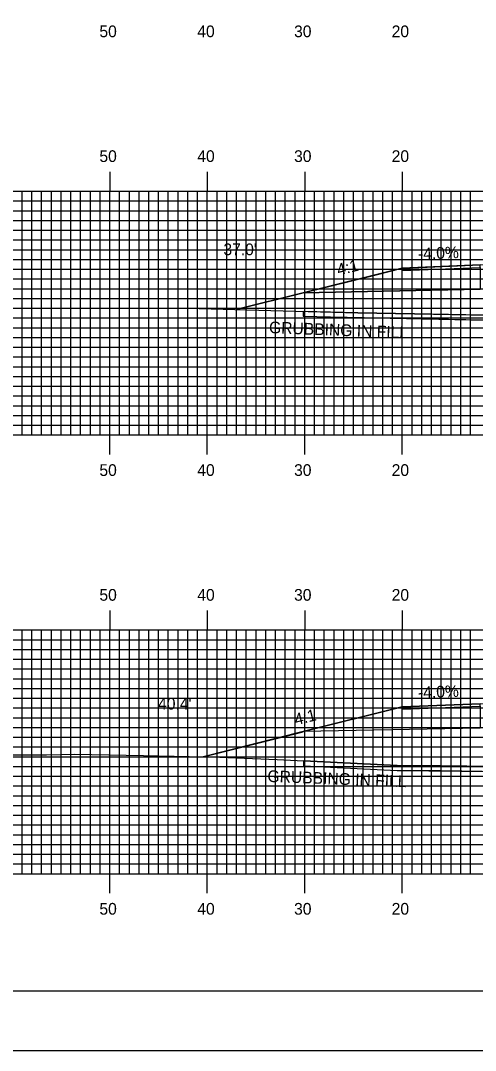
# Model space of a CAD drawing. Extents: x 1763759 to 1764102, y 442591 to 442811.
# Drawn here: x 1763865.2 to 1763911.8, y 442590.5 to 442696.2 of the extents above; entities that cross this region are included whole.
import ezdxf

# ---------------------------------------------------------------- set-up
doc = ezdxf.new("R2010")
doc.units = 0
for name, color, linetype in [('ANNOTATION', 7, 'Continuous'), ('BORDER', 7, 'Continuous'), ('D_Roadway_Centerline', 7, 'Continuous'), ('D_Roadway_Edge_Shoulder', 7, 'Continuous'), ('D_Roadway_SlopeLines', 7, 'Continuous'), ('D_Roadway_SubGrade', 7, 'Continuous'), ('D_Text_Standard', 7, 'Continuous'), ('GRUBBING IN FILL', 7, 'Continuous'), ('H_V ANNOTATION', 7, 'Continuous'), ('MAJOR', 7, 'Continuous'), ('MINOR', 7, 'Continuous'), ('PLOT BOUNDARY', 7, 'Continuous'), ('S_Roadway_Centerline', 7, 'Continuous')]:
    doc.layers.add(name, color=color, linetype=linetype)

msp = doc.modelspace()

# ---------------------------------------------------------------- linework, layer by layer
at = {"layer": 'BORDER'}
msp.add_lwpolyline([(1763774.72, 442596.67), (1764094.72, 442596.67), (1764094.72, 442806.67), (1763774.72, 442806.67)], close=True, dxfattribs=at)
at = {"layer": 'D_Roadway_Centerline'}
for points in [[(1763887.29, 442666.53), (1763894.14, 442668.24), (1763894.15, 442668.24), (1763901.63, 442670.11), (1763904.32, 442670.79), (1763906.87, 442670.89), (1763912.31, 442671.11), (1763912.32, 442671.11), (1763924.31, 442671.35), (1763924.32, 442671.35), (1763924.32, 442671.35), (1763936.32, 442671.27), (1763936.32, 442671.27), (1763940.22, 442671.11), (1763944.32, 442670.95), (1763944.33, 442670.95), (1763950.59, 442669.38), (1763954.49, 442668.4), (1763955.16, 442668.24), (1763956.32, 442667.95), (1763964.82, 442665.82), (1763964.98, 442665.78)], [(1763883.9, 442620.67), (1763894.14, 442623.23), (1763894.14, 442623.24), (1763904.32, 442625.78), (1763904.32, 442625.78), (1763912.31, 442626.1), (1763912.32, 442626.1), (1763919.08, 442626.24), (1763924.31, 442626.34), (1763924.32, 442626.34), (1763936.31, 442626.5), (1763936.32, 442626.5), (1763936.32, 442626.5), (1763944.32, 442626.18), (1763954.49, 442623.64), (1763954.49, 442623.63), (1763956.32, 442623.18), (1763957.04, 442623), (1763968.66, 442620.09)]]:
    msp.add_lwpolyline(points, dxfattribs=at)
at = {"layer": 'D_Roadway_Edge_Shoulder'}
for points in [[(1763912.32, 442671.11), (1763904.32, 442670.79), (1763904.32, 442670.54), (1763912.32, 442670.86)], [(1763912.32, 442626.1), (1763904.32, 442625.78), (1763904.32, 442625.53), (1763912.32, 442625.85)]]:
    msp.add_lwpolyline(points, close=True, dxfattribs=at)
at = {"layer": 'D_Roadway_SlopeLines'}
for points in [[(1763904.32, 442670.79), (1763894.14, 442668.24), (1763887.29, 442666.53)], [(1763904.32, 442625.78), (1763894.14, 442623.24), (1763883.9, 442620.67)]]:
    msp.add_lwpolyline(points, dxfattribs=at)
at = {"layer": 'D_Roadway_SubGrade'}
for points in [[(1763904.32, 442670.54), (1763912.32, 442670.86), (1763912.32, 442670.44), (1763912.32, 442668.61), (1763894.14, 442668.24), (1763904.32, 442670.79)], [(1763904.32, 442625.53), (1763912.32, 442625.85), (1763912.32, 442625.43), (1763912.32, 442623.6), (1763894.14, 442623.24), (1763904.32, 442625.78)]]:
    msp.add_lwpolyline(points, close=True, dxfattribs=at)
at = {"layer": 'GRUBBING IN FILL'}
for p, q in [((1763894.14, 442666.35), (1763894.14, 442665.85)), ((1763894.22, 442619.74), (1763894.22, 442620.24))]:
    msp.add_line(p, q, dxfattribs=at)
for points in [[(1763894.14, 442668.24), (1763912.32, 442668.61), (1763924.32, 442668.85), (1763936.32, 442668.77), (1763954.49, 442668.4)], [(1763894.14, 442665.85), (1763899.76, 442665.71), (1763911.39, 442665.49), (1763917.28, 442665.37), (1763922.81, 442665.34), (1763935.01, 442665.23), (1763940.12, 442665.08), (1763952.29, 442665.22), (1763953.27, 442665.24), (1763953.7, 442665.26), (1763954.47, 442665.25)], [(1763894.22, 442619.74), (1763903.78, 442619.27), (1763908.34, 442619.25), (1763918.82, 442619.1), (1763922.15, 442619.08), (1763924.62, 442619.11), (1763939.47, 442619.52), (1763954.47, 442619.78)]]:
    msp.add_lwpolyline(points, dxfattribs=at)
for points in [[(1763894.14, 442666.35), (1763894.14, 442665.85), (1763896.95, 442665.78), (1763905.58, 442665.6), (1763914.34, 442665.43), (1763920.05, 442665.35), (1763924.32, 442665.32), (1763924.32, 442665.82), (1763920.05, 442665.85), (1763914.34, 442665.93), (1763905.58, 442666.1), (1763899.76, 442666.21)], [(1763894.14, 442666.35), (1763894.14, 442665.85), (1763896.95, 442665.78), (1763905.58, 442665.6), (1763914.34, 442665.43), (1763920.05, 442665.35), (1763924.32, 442665.32), (1763924.32, 442665.82), (1763920.05, 442665.85), (1763914.34, 442665.93), (1763905.58, 442666.1), (1763899.76, 442666.21)], [(1763894.22, 442619.74), (1763903.78, 442619.27), (1763913.58, 442619.17), (1763916.38, 442619.14), (1763917.03, 442619.13), (1763918.6, 442619.1), (1763920.48, 442619.09), (1763924.32, 442619.1), (1763924.32, 442619.6), (1763920.48, 442619.59), (1763918.82, 442619.6), (1763913.58, 442619.67), (1763908.34, 442619.75), (1763903.78, 442619.77), (1763897.63, 442620.07), (1763894.22, 442620.24)], [(1763894.22, 442619.74), (1763903.78, 442619.27), (1763913.58, 442619.17), (1763916.38, 442619.14), (1763917.03, 442619.13), (1763918.6, 442619.1), (1763920.48, 442619.09), (1763924.32, 442619.1), (1763924.32, 442619.6), (1763920.48, 442619.59), (1763918.82, 442619.6), (1763913.58, 442619.67), (1763908.34, 442619.75), (1763903.78, 442619.77), (1763897.63, 442620.07), (1763894.22, 442620.24)]]:
    msp.add_lwpolyline(points, close=True, dxfattribs=at)
at = {"layer": 'MAJOR'}
for p, q in [((1763874.32, 442680.67), (1763874.32, 442678.67)), ((1763884.32, 442680.67), (1763884.32, 442678.67)), ((1763894.32, 442680.67), (1763894.32, 442678.67)), ((1763904.32, 442680.67), (1763904.32, 442678.67)), ((1763784.32, 442678.67), (1764064.32, 442678.67)), ((1763784.32, 442678.67), (1764064.32, 442678.67)), ((1763874.32, 442653.67), (1763874.32, 442678.67)), ((1763884.32, 442653.67), (1763884.32, 442678.67)), ((1763894.32, 442653.67), (1763894.32, 442678.67)), ((1763904.32, 442653.67), (1763904.32, 442678.67)), ((1763784.32, 442673.67), (1764064.32, 442673.67)), ((1763784.32, 442668.67), (1764064.32, 442668.67)), ((1763784.32, 442663.67), (1764064.32, 442663.67)), ((1763784.32, 442658.67), (1764064.32, 442658.67)), ((1763784.32, 442653.67), (1764064.32, 442653.67)), ((1763784.32, 442653.67), (1764064.32, 442653.67)), ((1763874.32, 442651.66), (1763874.32, 442653.67)), ((1763884.32, 442651.66), (1763884.32, 442653.67)), ((1763894.32, 442651.66), (1763894.32, 442653.67)), ((1763904.32, 442651.66), (1763904.32, 442653.67)), ((1763874.32, 442635.67), (1763874.32, 442633.67)), ((1763884.32, 442635.67), (1763884.32, 442633.67)), ((1763894.32, 442635.67), (1763894.32, 442633.67)), ((1763904.32, 442635.67), (1763904.32, 442633.67)), ((1763784.32, 442633.67), (1764064.32, 442633.67)), ((1763784.32, 442633.67), (1764064.32, 442633.67)), ((1763874.32, 442608.67), (1763874.32, 442633.67)), ((1763884.32, 442608.67), (1763884.32, 442633.67)), ((1763894.32, 442608.67), (1763894.32, 442633.67)), ((1763904.32, 442608.67), (1763904.32, 442633.67)), ((1763784.32, 442628.67), (1764064.32, 442628.67)), ((1763784.32, 442623.67), (1764064.32, 442623.67)), ((1763784.32, 442618.67), (1764064.32, 442618.67)), ((1763784.32, 442613.67), (1764064.32, 442613.67)), ((1763784.32, 442608.67), (1764064.32, 442608.67)), ((1763784.32, 442608.67), (1764064.32, 442608.67)), ((1763874.32, 442606.66), (1763874.32, 442608.67)), ((1763884.32, 442606.66), (1763884.32, 442608.67)), ((1763894.32, 442606.66), (1763894.32, 442608.67)), ((1763904.32, 442606.66), (1763904.32, 442608.67))]:
    msp.add_line(p, q, dxfattribs=at)
at = {"layer": 'MINOR'}
for p, q in [((1763865.32, 442653.67), (1763865.32, 442678.67)), ((1763866.32, 442653.67), (1763866.32, 442678.67)), ((1763867.32, 442653.67), (1763867.32, 442678.67)), ((1763868.32, 442653.67), (1763868.32, 442678.67)), ((1763869.32, 442653.67), (1763869.32, 442678.67)), ((1763870.32, 442653.67), (1763870.32, 442678.67)), ((1763871.32, 442653.67), (1763871.32, 442678.67)), ((1763872.32, 442653.67), (1763872.32, 442678.67)), ((1763873.32, 442653.67), (1763873.32, 442678.67)), ((1763875.32, 442653.67), (1763875.32, 442678.67)), ((1763876.32, 442653.67), (1763876.32, 442678.67)), ((1763877.32, 442653.67), (1763877.32, 442678.67)), ((1763878.32, 442653.67), (1763878.32, 442678.67)), ((1763879.32, 442653.67), (1763879.32, 442678.67)), ((1763880.32, 442653.67), (1763880.32, 442678.67)), ((1763881.32, 442653.67), (1763881.32, 442678.67)), ((1763882.32, 442653.67), (1763882.32, 442678.67)), ((1763883.32, 442653.67), (1763883.32, 442678.67)), ((1763885.32, 442653.67), (1763885.32, 442678.67)), ((1763886.32, 442653.67), (1763886.32, 442678.67)), ((1763887.32, 442653.67), (1763887.32, 442678.67)), ((1763888.32, 442653.67), (1763888.32, 442678.67)), ((1763889.32, 442653.67), (1763889.32, 442678.67)), ((1763890.32, 442653.67), (1763890.32, 442678.67)), ((1763891.32, 442653.67), (1763891.32, 442678.67)), ((1763892.32, 442653.67), (1763892.32, 442678.67)), ((1763893.32, 442653.67), (1763893.32, 442678.67)), ((1763895.32, 442653.67), (1763895.32, 442678.67)), ((1763896.32, 442653.67), (1763896.32, 442678.67)), ((1763897.32, 442653.67), (1763897.32, 442678.67)), ((1763898.32, 442653.67), (1763898.32, 442678.67)), ((1763899.32, 442653.67), (1763899.32, 442678.67)), ((1763900.32, 442653.67), (1763900.32, 442678.67)), ((1763901.32, 442653.67), (1763901.32, 442678.67)), ((1763902.32, 442653.67), (1763902.32, 442678.67)), ((1763903.32, 442653.67), (1763903.32, 442678.67)), ((1763905.32, 442653.67), (1763905.32, 442678.67)), ((1763906.32, 442653.67), (1763906.32, 442678.67)), ((1763907.32, 442653.67), (1763907.32, 442678.67)), ((1763908.32, 442653.67), (1763908.32, 442678.67)), ((1763909.32, 442653.67), (1763909.32, 442678.67)), ((1763910.32, 442653.67), (1763910.32, 442678.67)), ((1763911.32, 442653.67), (1763911.32, 442678.67)), ((1763784.32, 442677.67), (1764064.32, 442677.67)), ((1763784.32, 442676.67), (1764064.32, 442676.67)), ((1763784.32, 442675.67), (1764064.32, 442675.67)), ((1763784.32, 442674.67), (1764064.32, 442674.67)), ((1763784.32, 442672.67), (1764064.32, 442672.67)), ((1763784.32, 442671.67), (1764064.32, 442671.67)), ((1763784.32, 442670.67), (1764064.32, 442670.67)), ((1763784.32, 442669.67), (1764064.32, 442669.67)), ((1763784.32, 442667.67), (1764064.32, 442667.67)), ((1763784.32, 442666.67), (1764064.32, 442666.67)), ((1763784.32, 442665.67), (1764064.32, 442665.67)), ((1763784.32, 442664.67), (1764064.32, 442664.67)), ((1763784.32, 442662.67), (1764064.32, 442662.67)), ((1763784.32, 442661.67), (1764064.32, 442661.67)), ((1763784.32, 442660.67), (1764064.32, 442660.67)), ((1763784.32, 442659.67), (1764064.32, 442659.67)), ((1763784.32, 442657.67), (1764064.32, 442657.67)), ((1763784.32, 442656.67), (1764064.32, 442656.67)), ((1763784.32, 442655.67), (1764064.32, 442655.67)), ((1763784.32, 442654.67), (1764064.32, 442654.67)), ((1763865.32, 442608.67), (1763865.32, 442633.67)), ((1763866.32, 442608.67), (1763866.32, 442633.67)), ((1763867.32, 442608.67), (1763867.32, 442633.67)), ((1763868.32, 442608.67), (1763868.32, 442633.67)), ((1763869.32, 442608.67), (1763869.32, 442633.67)), ((1763870.32, 442608.67), (1763870.32, 442633.67)), ((1763871.32, 442608.67), (1763871.32, 442633.67)), ((1763872.32, 442608.67), (1763872.32, 442633.67)), ((1763873.32, 442608.67), (1763873.32, 442633.67)), ((1763875.32, 442608.67), (1763875.32, 442633.67)), ((1763876.32, 442608.67), (1763876.32, 442633.67)), ((1763877.32, 442608.67), (1763877.32, 442633.67)), ((1763878.32, 442608.67), (1763878.32, 442633.67)), ((1763879.32, 442608.67), (1763879.32, 442633.67)), ((1763880.32, 442608.67), (1763880.32, 442633.67)), ((1763881.32, 442608.67), (1763881.32, 442633.67)), ((1763882.32, 442608.67), (1763882.32, 442633.67)), ((1763883.32, 442608.67), (1763883.32, 442633.67)), ((1763885.32, 442608.67), (1763885.32, 442633.67)), ((1763886.32, 442608.67), (1763886.32, 442633.67)), ((1763887.32, 442608.67), (1763887.32, 442633.67)), ((1763888.32, 442608.67), (1763888.32, 442633.67)), ((1763889.32, 442608.67), (1763889.32, 442633.67)), ((1763890.32, 442608.67), (1763890.32, 442633.67)), ((1763891.32, 442608.67), (1763891.32, 442633.67)), ((1763892.32, 442608.67), (1763892.32, 442633.67)), ((1763893.32, 442608.67), (1763893.32, 442633.67)), ((1763895.32, 442608.67), (1763895.32, 442633.67)), ((1763896.32, 442608.67), (1763896.32, 442633.67)), ((1763897.32, 442608.67), (1763897.32, 442633.67)), ((1763898.32, 442608.67), (1763898.32, 442633.67)), ((1763899.32, 442608.67), (1763899.32, 442633.67)), ((1763900.32, 442608.67), (1763900.32, 442633.67)), ((1763901.32, 442608.67), (1763901.32, 442633.67)), ((1763902.32, 442608.67), (1763902.32, 442633.67)), ((1763903.32, 442608.67), (1763903.32, 442633.67)), ((1763905.32, 442608.67), (1763905.32, 442633.67)), ((1763906.32, 442608.67), (1763906.32, 442633.67)), ((1763907.32, 442608.67), (1763907.32, 442633.67)), ((1763908.32, 442608.67), (1763908.32, 442633.67)), ((1763909.32, 442608.67), (1763909.32, 442633.67)), ((1763910.32, 442608.67), (1763910.32, 442633.67)), ((1763911.32, 442608.67), (1763911.32, 442633.67)), ((1763784.32, 442632.67), (1764064.32, 442632.67)), ((1763784.32, 442631.67), (1764064.32, 442631.67)), ((1763784.32, 442630.67), (1764064.32, 442630.67)), ((1763784.32, 442629.67), (1764064.32, 442629.67)), ((1763784.32, 442627.67), (1764064.32, 442627.67)), ((1763784.32, 442626.67), (1764064.32, 442626.67)), ((1763784.32, 442625.67), (1764064.32, 442625.67)), ((1763784.32, 442624.67), (1764064.32, 442624.67)), ((1763784.32, 442622.67), (1764064.32, 442622.67)), ((1763784.32, 442621.67), (1764064.32, 442621.67)), ((1763784.32, 442620.67), (1764064.32, 442620.67)), ((1763784.32, 442619.67), (1764064.32, 442619.67)), ((1763784.32, 442617.67), (1764064.32, 442617.67)), ((1763784.32, 442616.67), (1764064.32, 442616.67)), ((1763784.32, 442615.67), (1764064.32, 442615.67)), ((1763784.32, 442614.67), (1764064.32, 442614.67)), ((1763784.32, 442612.67), (1764064.32, 442612.67)), ((1763784.32, 442611.67), (1764064.32, 442611.67)), ((1763784.32, 442610.67), (1764064.32, 442610.67)), ((1763784.32, 442609.67), (1764064.32, 442609.67))]:
    msp.add_line(p, q, dxfattribs=at)
at = {"layer": 'PLOT BOUNDARY'}
msp.add_lwpolyline([(1763758.53, 442590.55), (1764098.53, 442590.55), (1764098.53, 442810.55), (1763758.53, 442810.55)], close=True, dxfattribs=at)
at = {"layer": 'S_Roadway_Centerline'}
for points in [[(1763863.88, 442666.68), (1763865.48, 442666.68), (1763869.39, 442666.69), (1763882.25, 442666.67), (1763890.84, 442666.43), (1763899.76, 442666.21), (1763911.39, 442665.99), (1763917.28, 442665.87), (1763922.81, 442665.84), (1763935.01, 442665.73), (1763940.12, 442665.58), (1763952.29, 442665.72), (1763953.27, 442665.74), (1763953.7, 442665.76), (1763954.72, 442665.75), (1763971.09, 442665.8)], [(1763860.52, 442620.85), (1763867.82, 442620.86), (1763870.65, 442620.92), (1763877.79, 442620.81), (1763885.59, 442620.64), (1763891.48, 442620.37), (1763903.78, 442619.77), (1763908.34, 442619.75), (1763918.82, 442619.6), (1763922.15, 442619.58), (1763924.62, 442619.61), (1763939.47, 442620.02), (1763954.56, 442620.28), (1763957.18, 442620.29), (1763960.52, 442620.37), (1763975.15, 442619.87)]]:
    msp.add_lwpolyline(points, dxfattribs=at)

# ---------------------------------------------------------------- texts
at = {"layer": 'ANNOTATION'}
for s, rotation, p in [('-4.0%', 2.2906, (1763905.95, 442671.65)), ('4:1', 14.0336, (1763897.77, 442670.01)), ('-4.0%', 2.2905, (1763905.95, 442626.65)), ('4:1', 14.0394, (1763893.42, 442623.88))]:
    msp.add_text(s, height=1.2, rotation=rotation, dxfattribs=at).set_placement(p)
at = {"layer": 'D_Text_Standard'}
for s, p in [("37.0'", (1763885.97, 442672.11)), ("40.4'", (1763879.27, 442625.51))]:
    msp.add_text(s, height=1.2, dxfattribs=at).set_placement(p)
at = {"layer": 'GRUBBING IN FILL'}
for p in [(1763890.63, 442664.12), (1763890.47, 442618.09)]:
    msp.add_text('GRUBBING IN FILL', height=1.2, rotation=357.7981, dxfattribs=at).set_placement(p)
at = {"layer": 'H_V ANNOTATION'}
for s, p in [('50', (1763873.25, 442694.47)), ('40', (1763883.29, 442694.47)), ('30', (1763893.22, 442694.47)), ('20', (1763903.23, 442694.47)), ('50', (1763873.25, 442681.67)), ('40', (1763883.29, 442681.67)), ('30', (1763893.22, 442681.67)), ('20', (1763903.23, 442681.67)), ('50', (1763873.25, 442649.47)), ('40', (1763883.29, 442649.47)), ('30', (1763893.22, 442649.47)), ('20', (1763903.23, 442649.47)), ('50', (1763873.25, 442636.67)), ('40', (1763883.29, 442636.67)), ('30', (1763893.22, 442636.67)), ('20', (1763903.23, 442636.67)), ('50', (1763873.25, 442604.47)), ('40', (1763883.29, 442604.47)), ('30', (1763893.22, 442604.47)), ('20', (1763903.23, 442604.47))]:
    msp.add_text(s, height=1.2, dxfattribs=at).set_placement(p)

doc.saveas('drawing.dxf')
